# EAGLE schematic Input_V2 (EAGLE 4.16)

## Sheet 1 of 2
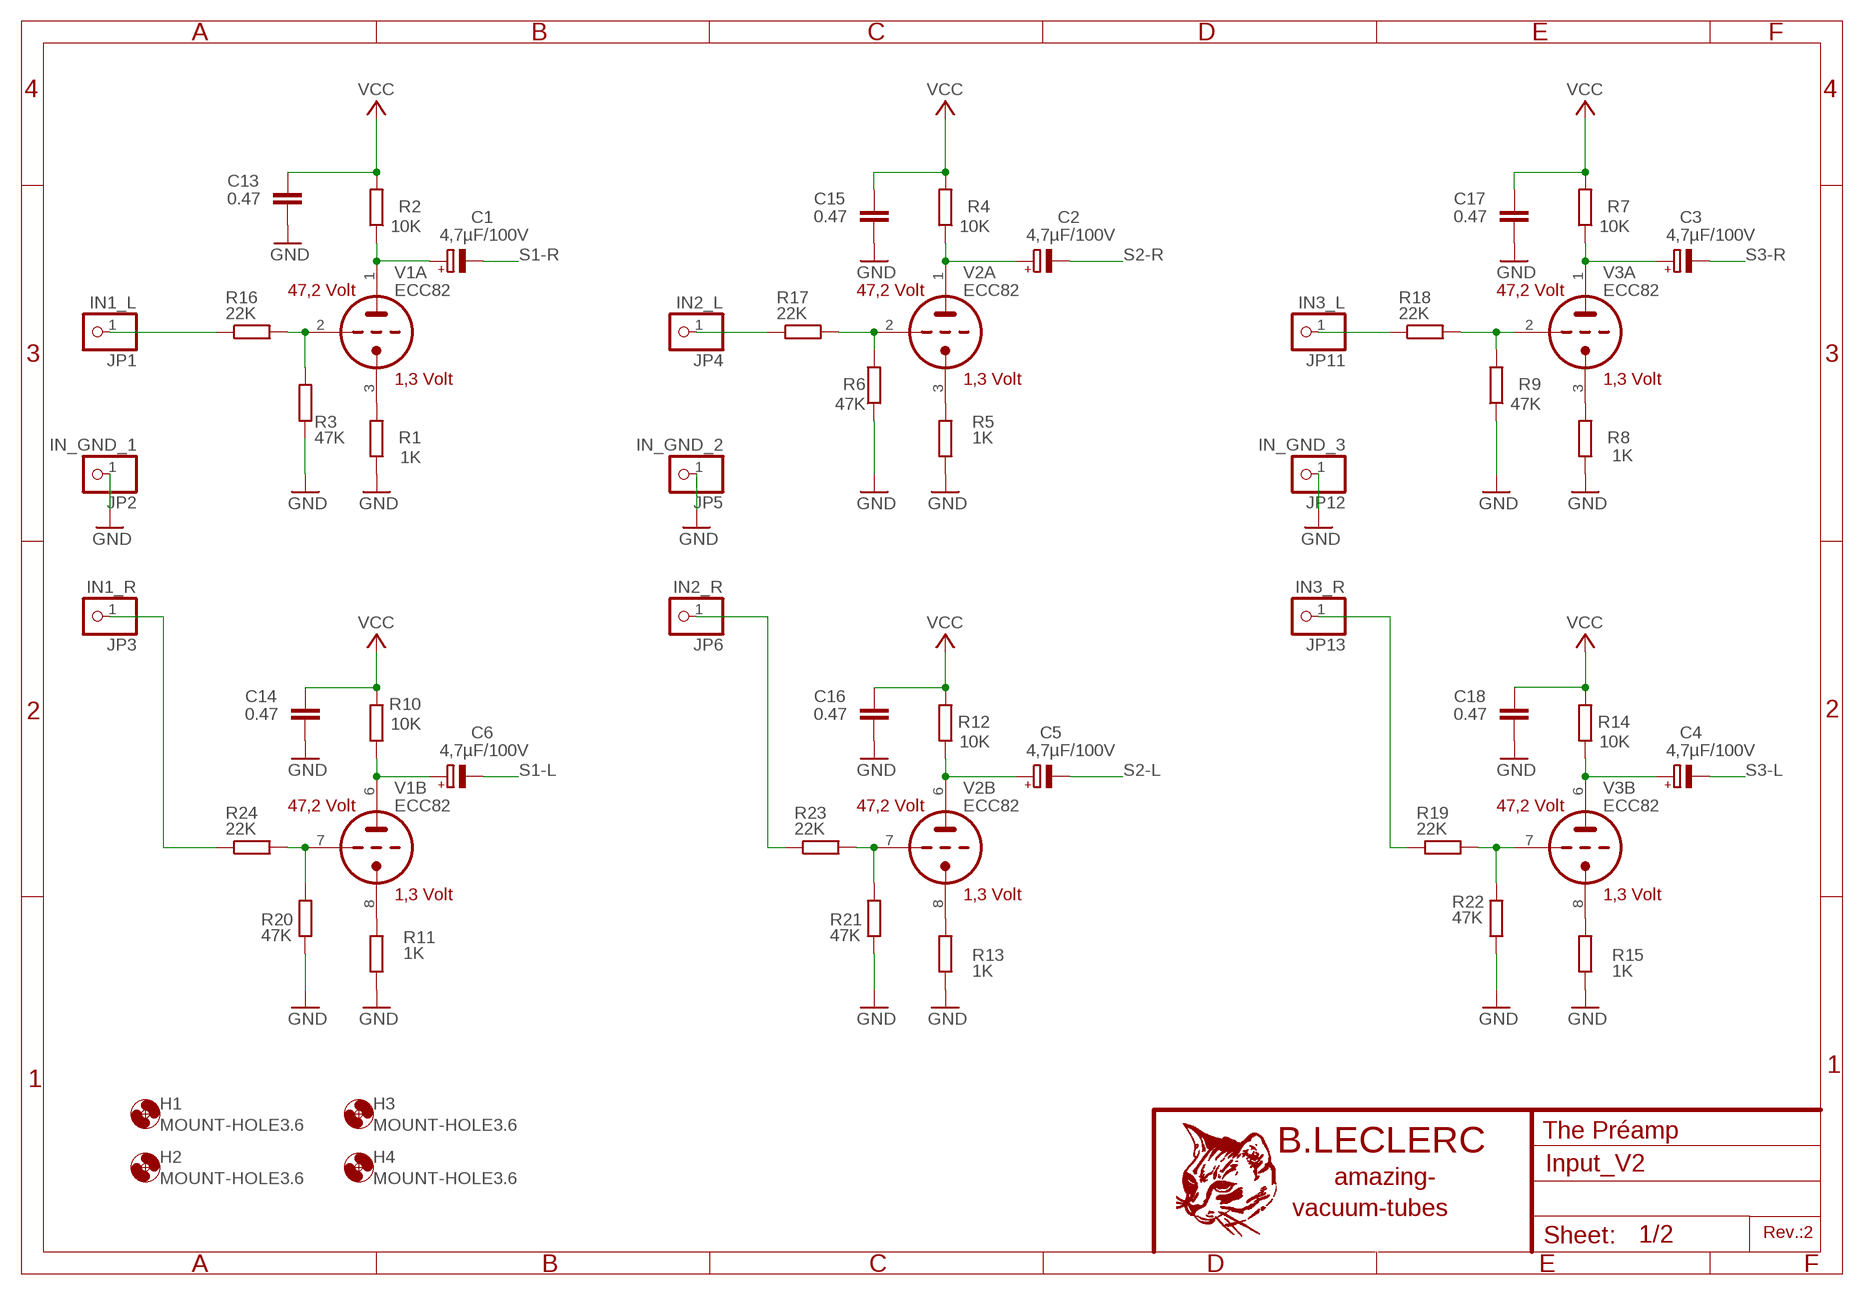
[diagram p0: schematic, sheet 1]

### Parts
C1  4,7µF/100V  CPOL-EUE5-8.5  [E5-8,5]
C2  4,7µF/100V  CPOL-EUE5-8.5  [E5-8,5]
C3  4,7µF/100V  CPOL-EUE5-8.5  [E5-8,5]
C4  4,7µF/100V  CPOL-EUE5-8.5  [E5-8,5]
C5  4,7µF/100V  CPOL-EUE5-8.5  [E5-8,5]
C6  4,7µF/100V  CPOL-EUE5-8.5  [E5-8,5]
C13  0.47  C-EU075-042X103  [C075-042X103]
C14  0.47  C-EU075-042X103  [C075-042X103]
C15  0.47  C-EU075-042X103  [C075-042X103]
C16  0.47  C-EU075-042X103  [C075-042X103]
C17  0.47  C-EU075-042X103  [C075-042X103]
C18  0.47  C-EU075-042X103  [C075-042X103]
H1  MOUNT-HOLE3.6  [3,6]
H2  MOUNT-HOLE3.6  [3,6]
H3  MOUNT-HOLE3.6  [3,6]
H4  MOUNT-HOLE3.6  [3,6]
JP1  IN1_L  PINHD-1X1  [1X01]
JP2  IN_GND_1  PINHD-1X1  [1X01]
JP3  IN1_R  PINHD-1X1  [1X01]
JP4  IN2_L  PINHD-1X1  [1X01]
JP5  IN_GND_2  PINHD-1X1  [1X01]
JP6  IN2_R  PINHD-1X1  [1X01]
JP11  IN3_L  PINHD-1X1  [1X01]
JP12  IN_GND_3  PINHD-1X1  [1X01]
JP13  IN3_R  PINHD-1X1  [1X01]
R1  1K  R-EU_0207/10  [0207/10]
R2  10K  R-EU_0207/10  [0207/10]
R3  47K  R-EU_0207/10  [0207/10]
R4  10K  R-EU_0207/10  [0207/10]
R5  1K  R-EU_0207/10  [0207/10]
R6  47K  R-EU_0207/10  [0207/10]
R7  10K  R-EU_0207/10  [0207/10]
R8  1K  R-EU_0207/10  [0207/10]
R9  47K  R-EU_0207/10  [0207/10]
R10  10K  R-EU_0207/10  [0207/10]
R11  1K  R-EU_0207/10  [0207/10]
R12  10K  R-EU_0207/10  [0207/10]
R13  1K  R-EU_0207/10  [0207/10]
R14  10K  R-EU_0207/10  [0207/10]
R15  1K  R-EU_0207/10  [0207/10]
R16  22K  R-EU_0207/10  [0207/10]
R17  22K  R-EU_0207/10  [0207/10]
R18  22K  R-EU_0207/10  [0207/10]
R19  22K  R-EU_0207/10  [0207/10]
R20  47K  R-EU_0207/10  [0207/10]
R21  47K  R-EU_0207/10  [0207/10]
R22  47K  R-EU_0207/10  [0207/10]
R23  22K  R-EU_0207/10  [0207/10]
R24  22K  R-EU_0207/10  [0207/10]
V1  ECC82  ECC82-P  [NOVAL]
V2  ECC82  ECC82-P  [NOVAL]
V3  ECC82  ECC82-P  [NOVAL]

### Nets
GND: C13.2 C14.2 C15.2 C16.2 C17.2 C18.2 JP2.1 JP5.1 JP12.1 R1.1 R3.1 R5.1 R6.1 R8.1 R9.1 R11.1 R13.1 R15.1 R20.1 R21.1 R22.1 ; also sheet 2
N$1: C2.+ R4.1 V2.1(A:TA)
N$2: C3.+ R7.1 V3.1(A:TA)
N$3: R8.2 V3.3(A:TK)
N$4: C6.+ R10.1 V1.6(B:TA)
N$5: R11.2 V1.8(B:TK)
N$7: R13.2 V2.8(B:TK)
N$8: C4.+ R14.1 V3.6(B:TA)
N$9: R15.2 V3.8(B:TK)
N$10: R1.2 V1.3(A:TK)
N$11: R3.2 R16.2 V1.2(A:TG)
N$12: C1.+ R2.1 V1.1(A:TA)
N$13: JP1.1 R16.1
N$14: JP4.1 R17.1
N$15: R5.2 V2.3(A:TK)
N$16: JP11.1 R18.1
N$17: JP3.1 R24.1
N$18: R6.2 R17.2 V2.2(A:TG)
N$19: JP6.1 R23.1
N$20: R20.2 R24.2 V1.7(B:TG)
N$21: R9.2 R18.2 V3.2(A:TG)
N$22: JP13.1 R19.1
N$25: R21.2 R23.2 V2.7(B:TG)
N$27: R19.2 R22.2 V3.7(B:TG)
N$73: C5.+ R12.1 V2.6(B:TA)
S1-L: C6.- ; also sheet 2
S1-R: C1.- ; also sheet 2
S2-L: C5.- ; also sheet 2
S2-R: C2.- ; also sheet 2
S3-L: C4.- ; also sheet 2
S3-R: C3.- ; also sheet 2
VCC: C13.1 C14.1 C15.1 C16.1 C17.1 C18.1 R2.2 R4.2 R7.2 R10.2 R12.2 R14.2 ; also sheet 2

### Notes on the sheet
- 47,2 Volt | 47,2 Volt | 47,2 Volt
- 1,3 Volt | 1,3 Volt | 1,3 Volt
- 47,2 Volt | 47,2 Volt | 47,2 Volt
- 1,3 Volt | 1,3 Volt | 1,3 Volt
- The Préamp
- Rev.:2

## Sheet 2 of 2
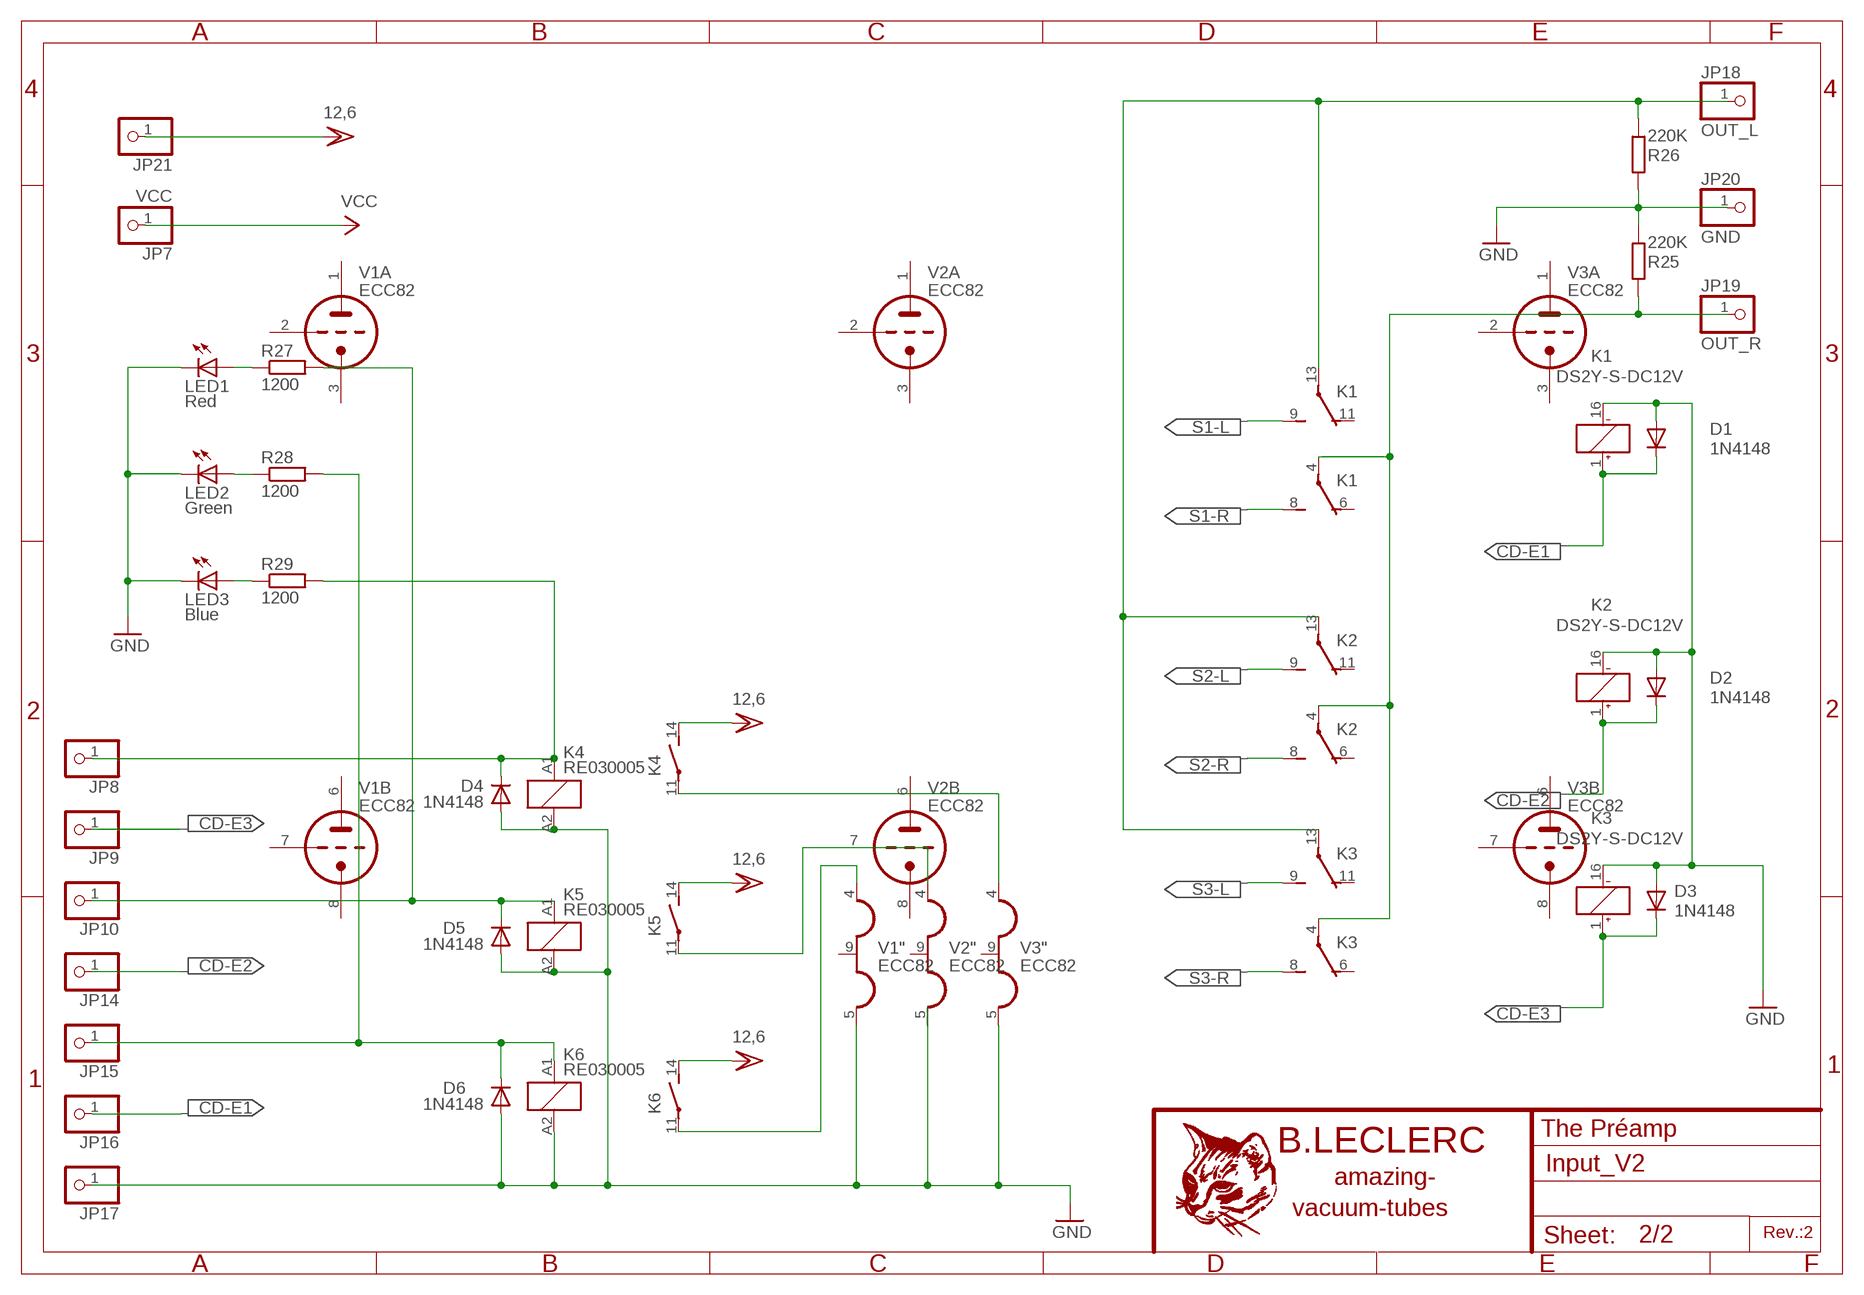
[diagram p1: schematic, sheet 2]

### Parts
D1  1N4148  DIODE-SMB  [SMB]
D2  1N4148  DIODE-SMB  [SMB]
D3  1N4148  DIODE-SMB  [SMB]
D4  1N4148  DIODE-SMB  [SMB]
D5  1N4148  DIODE-SMB  [SMB]
D6  1N4148  DIODE-SMB  [SMB]
JP7  VCC  PINHD-1X1  [1X01]
JP8  PINHD-1X1  [1X01]
JP9  PINHD-1X1  [1X01]
JP10  PINHD-1X1  [1X01]
JP14  PINHD-1X1  [1X01]
JP15  PINHD-1X1  [1X01]
JP16  PINHD-1X1  [1X01]
JP17  PINHD-1X1  [1X01]
JP18  OUT_L  PINHD-1X1  [1X01]
JP19  OUT_R  PINHD-1X1  [1X01]
JP20  GND  PINHD-1X1  [1X01]
JP21  PINHD-1X1  [1X01]
K1  DS2Y-S-DC12V  [DS2Y]
K2  DS2Y-S-DC12V  [DS2Y]
K3  DS2Y-S-DC12V  [DS2Y]
K4  RE030005  [RE-SCHRACK]
K5  RE030005  [RE-SCHRACK]
K6  RE030005  [RE-SCHRACK]
LED1  Red  LEDCHIPLED_1206  [CHIPLED_1206]
LED2  Green  LEDCHIPLED_1206  [CHIPLED_1206]
LED3  Blue  LEDCHIPLED_1206  [CHIPLED_1206]
R25  220K  R-EU_0207/10  [0207/10]
R26  220K  R-EU_0207/10  [0207/10]
R27  1200  R-EU_M1206  [M1206]
R28  1200  R-EU_M1206  [M1206]
R29  1200  R-EU_M1206  [M1206]

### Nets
CD-E1: D1.C JP16.1 K1.1(1:+)
CD-E2: D2.C JP14.1 K2.1(1:+)
CD-E3: D3.C JP9.1 K3.1(1:+)
GND: D1.A D2.A D3.A D4.A D5.A D6.A JP17.1 JP20.1 K1.16(1:-) K2.16(1:-) K3.16(1:-) K4.A2 K5.A2 K6.A2 LED1.C LED2.C LED3.C R25.1 R26.2 V1.5(":H3) V3.5(":H3) ; also sheet 1
N$6: D6.C JP15.1 K6.A1 R28.2
N$23: LED3.A R29.1
N$24: LED2.A R28.1
N$26: LED1.A R27.1
N$29: D5.C JP10.1 K5.A1 R27.2
N$31: D4.C JP8.1 K4.A1 R29.2
N$36: JP19.1 K1.4(2:P) K2.4(2:P) K3.4(2:P) R25.2
N$37: JP18.1 K1.13(3:P) K2.13(3:P) K3.13(3:P) R26.1
N$239: K4.11(2:P) V3.4(":H1)
N$240: K6.11(2:P) V1.4(":H1)
N$241: K5.11(2:P) V2.4(":H1)
S1-L: K1.9(3:S) ; also sheet 1
S1-R: K1.8(2:S) ; also sheet 1
S2-L: K2.9(3:S) ; also sheet 1
S2-R: K2.8(2:S) ; also sheet 1
S3-L: K3.9(3:S) ; also sheet 1
S3-R: K3.8(2:S) ; also sheet 1
VCC: JP7.1 ; also sheet 1
VCC/2: JP21.1 K4.14(2:S) K5.14(2:S) K6.14(2:S) ; supply symbol labelled 12,6
Unconnected: K1.6(2:O) K1.11(3:O) K2.6(2:O) K2.11(3:O) K3.6(2:O) K3.11(3:O) V1.9(":H2) V2.5(":H3) V2.9(":H2) V3.9(":H2)

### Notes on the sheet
- The Préamp
- Rev.:2

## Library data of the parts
C1-C6 = rcl:CPOL-EU: POLARIZED CAPACITOR, European symbol
C13-C18 = rcl:C-EU: CAPACITOR, European symbol
D1-D6 = diode:DIODE-: DIODE
H1-H4 = holes:MOUNT-HOLE: MOUNTING HOLE with drill center marker
JP1-JP21 = pinhead:PINHD-1X1: PIN HEADER
K1-K3 = relay:DS2Y-S-DC*: MINIATURE RELAY NAiS Source: http://www.mew-europe.com/.. en_ds_61005_0023.pdf
K4-K6 = relay:RE03*: Miniature PCB Relay 1 pole 6 A SCHRACK Source: http://www.schrack.com/.. 5812.pdf
LED1-LED3 = led:LED: LED
R1-R29 = rcl:R-EU_: RESISTOR, European symbol
V1-V3 = tubes:ECC82-P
